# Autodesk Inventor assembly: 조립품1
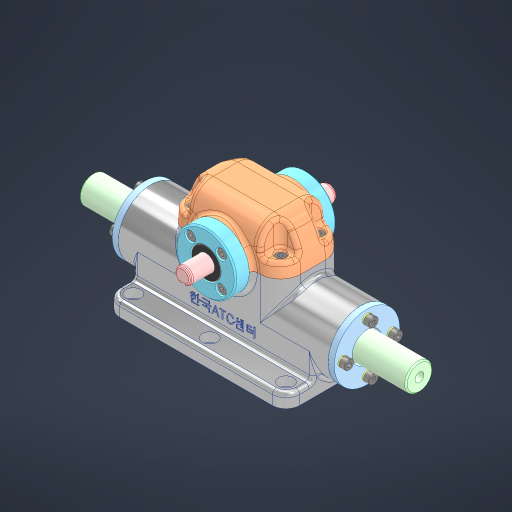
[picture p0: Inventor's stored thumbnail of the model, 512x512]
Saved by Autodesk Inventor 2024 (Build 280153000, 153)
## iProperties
Created: 2024-06
Part Number: 조립품1
Document SubType Name: Assembly
Designer: kh_501
Author: kh_501
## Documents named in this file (13)
- C:\Users\kh_501\Desktop\740604V1008 (1)\조립품1.iam
- C:\Users\kh_501\Desktop\740604V1008 (1)\본체.ipt
- C:\Users\kh_501\Desktop\740604V1008 (1)\깊은 홈 볼 베어링 6901\깊은 홈 볼 베어링 6901.ipt
- C:\Users\kh_501\Desktop\740604V1008 (1)\랙\랙.ipt
- C:\Users\kh_501\Desktop\740604V1008 (1)\베어링 커버\베어링 커버.ipt
- C:\Users\kh_501\Desktop\740604V1008 (1)\부시 커버\부시 커버.ipt
- C:\Users\kh_501\Desktop\740604V1008 (1)\스프링 와셔 M4\스프링 와셔 M4.ipt
- C:\Users\kh_501\Desktop\740604V1008 (1)\오일레스 부시\오일레스 부시.ipt
- C:\Users\kh_501\Desktop\740604V1008 (1)\오일실 12 22 7\오일실 12 22 7.ipt
- C:\Users\kh_501\Desktop\740604V1008 (1)\윗커버\윗커버.ipt
- C:\Users\kh_501\Desktop\740604V1008 (1)\육각 소켓 머리 볼트 M4x10\육각 소켓 머리 볼트 M4x10.ipt
- C:\Users\kh_501\Desktop\740604V1008 (1)\칼라\칼라.ipt
- C:\Users\kh_501\Desktop\740604V1008 (1)\피니언\피니언.ipt
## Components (1 placed, 1 different names)
1. 피니언:1 — 각도:9
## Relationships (1: Angle 1)
- 각도:9 [Angle]: 피니언:1
